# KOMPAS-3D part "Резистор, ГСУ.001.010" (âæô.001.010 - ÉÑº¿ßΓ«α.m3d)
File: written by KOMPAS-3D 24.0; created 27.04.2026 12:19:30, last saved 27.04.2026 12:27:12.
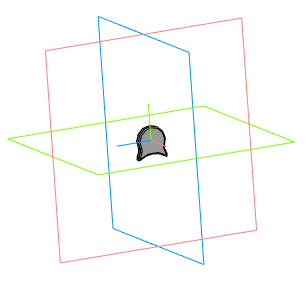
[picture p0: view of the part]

Document properties: Автор: User7; Полное имя файла: C:\Users\User7\Desktop\олимп\ГСУ.001.010 - Резистор.m3d

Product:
- Part/product: Резистор  | designation ГСУ.001.010
    Масса: 0.000476

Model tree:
1. Эскиз:1
2. Элемент выдавливания:1
     Расстояние 1 = 1.5
3. Скругление:1  (with: Ребро.Элемент выдавливания:1)
     Радиус = 0.1
4. Зеркальный массив:1
5. Экземпляр ( 1 )
6. Экземпляр ( 2 )  (with: Элемент выдавливания:1, Скругление:1)
7. Скругление:2  (with: Ребро.Элемент выдавливания:1)
     Радиус = 0.3

Expressions: 7.7-6.85/2; 6.5-6.85/2
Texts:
  ГСУ.001.010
